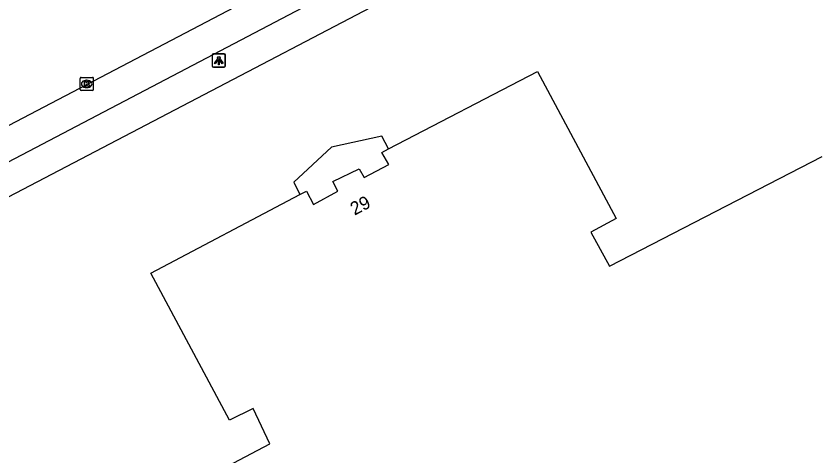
# Model space of a CAD drawing. Extents: x 157692 to 159670, y 381454 to 383289.
# Drawn here: x 158417.5 to 158478.6, y 381859.1 to 381892.5 of the extents above; entities that cross this region are included whole.
import ezdxf

# ---------------------------------------------------------------- set-up
doc = ezdxf.new("R2010")
doc.units = 0
for name, color, linetype in [('IMGEO_Kolk', 7, 'Continuous'), ('IMGEO_Lichtpunt', 7, 'Continuous'), ('IMGEO_Pand', 7, 'Continuous'), ('IMGEO_Pand_nummerreeks', 7, 'Continuous'), ('IMGEO_Pand_overbouw', 7, 'Continuous'), ('IMGEO_Rijbaan_lokaal_gesloten', 7, 'Continuous'), ('IMGEO_Voetpad_open', 7, 'Continuous')]:
    doc.layers.add(name, color=color, linetype=linetype)

msp = doc.modelspace()

# ---------------------------------------------------------------- linework, layer by layer
at = {"layer": 'IMGEO_Kolk'}
for p, q in [((158422.327, 381886.896), (158422.327, 381887.748)), ((158422.402, 381887.822), (158423.254, 381887.822)), ((158422.815, 381887.602), (158422.84, 381887.602)), ((158423.328, 381887.748), (158423.328, 381886.896)), ((158422.838, 381887.042), (158422.813, 381887.042)), ((158423.254, 381886.822), (158422.402, 381886.822))]:
    msp.add_line(p, q, dxfattribs=at)
for points in [[(158422.327, 381886.896), (158422.327, 381887.748)], [(158422.402, 381887.822), (158423.254, 381887.822)], [(158423.328, 381887.748), (158423.328, 381886.896)], [(158422.648, 381887.522), (158422.771, 381887.522), (158422.771, 381887.371), (158422.901, 381887.522), (158423.065, 381887.522), (158422.919, 381887.371), (158423.072, 381887.122), (158422.92, 381887.122), (158422.835, 381887.286), (158422.771, 381887.219), (158422.771, 381887.122), (158422.648, 381887.122), (158422.648, 381887.522)], [(158423.254, 381886.822), (158422.402, 381886.822)]]:
    msp.add_lwpolyline(points, dxfattribs=at)
for centre, start, end in [((158422.404, 381887.746), 91.55205, 178.44795), ((158422.404, 381887.746), 91.55205, 178.44795), ((158423.252, 381887.746), 1.55205, 88.44795), ((158423.252, 381887.746), 1.55205, 88.44795), ((158422.404, 381886.898), 181.55205, 268.44795), ((158422.404, 381886.898), 181.55205, 268.44795), ((158423.252, 381886.898), 271.55205, 358.44795), ((158423.252, 381886.898), 271.55205, 358.44795)]:
    msp.add_arc(centre, 0.0765, start, end, dxfattribs=at)
for centre, major_axis, ratio, start_param, end_param in [((158422.814, 381887.322), (-0.387, 0.002), 0.722429, 4.712389, 7.853982), ((158422.839, 381887.322), (-0.39, 0.002), 0.717154, 1.570796, 4.712389)]:
    msp.add_ellipse(centre, major_axis=major_axis, ratio=ratio, start_param=start_param, end_param=end_param, dxfattribs=at)
at = {"layer": 'IMGEO_Lichtpunt'}
for p, q in [((158432.34, 381889.486), (158432.34, 381888.679)), ((158432.34, 381889.486), (158432.34, 381888.679)), ((158432.351, 381889.512), (158432.351, 381888.705)), ((158432.351, 381889.512), (158432.351, 381888.705)), ((158433.242, 381889.581), (158432.434, 381889.581)), ((158433.242, 381889.581), (158432.434, 381889.581)), ((158433.253, 381889.607), (158432.445, 381889.607)), ((158433.253, 381889.607), (158432.445, 381889.607)), ((158433.336, 381888.679), (158433.336, 381889.486)), ((158433.336, 381888.679), (158433.336, 381889.486)), ((158433.347, 381888.705), (158433.347, 381889.512)), ((158433.347, 381888.705), (158433.347, 381889.512)), ((158432.434, 381888.585), (158433.242, 381888.585)), ((158432.434, 381888.585), (158433.242, 381888.585)), ((158432.445, 381888.611), (158433.253, 381888.611)), ((158432.445, 381888.611), (158433.253, 381888.611))]:
    msp.add_line(p, q, dxfattribs=at)
for points in [[(158432.714, 381889.15), (158432.753, 381889.122), (158432.565, 381888.86), (158432.527, 381888.887), (158432.714, 381889.15)], [(158432.725, 381889.176), (158432.764, 381889.148), (158432.576, 381888.886), (158432.538, 381888.913), (158432.725, 381889.176)], [(158432.816, 381889.102), (158432.863, 381889.102), (158432.863, 381888.78), (158432.816, 381888.78), (158432.816, 381889.102)], [(158432.827, 381889.128), (158432.874, 381889.128), (158432.874, 381888.806), (158432.827, 381888.806), (158432.827, 381889.128)], [(158432.926, 381889.122), (158432.964, 381889.149), (158433.151, 381888.887), (158433.112, 381888.859), (158432.926, 381889.122)], [(158432.937, 381889.148), (158432.975, 381889.175), (158433.162, 381888.913), (158433.123, 381888.885), (158432.937, 381889.148)]]:
    msp.add_lwpolyline(points, dxfattribs=at)
for centre in [(158432.85, 381889.31), (158432.839, 381889.284)]:
    msp.add_circle(centre, 0.0994, dxfattribs=at)
for centre, start, end in [((158432.434, 381889.486), 90, 180), ((158432.434, 381889.486), 90, 180), ((158432.445, 381889.512), 90, 180), ((158432.445, 381889.512), 90, 180), ((158433.242, 381889.486), 0, 90), ((158433.242, 381889.486), 0, 90), ((158433.253, 381889.512), 0, 90), ((158433.253, 381889.512), 0, 90), ((158432.434, 381888.679), 180, 270), ((158432.434, 381888.679), 180, 270), ((158432.445, 381888.705), 180, 270), ((158432.445, 381888.705), 180, 270), ((158433.242, 381888.679), 270, 0), ((158433.242, 381888.679), 270, 360), ((158433.253, 381888.705), 270, 0), ((158433.253, 381888.705), 270, 360)]:
    msp.add_arc(centre, 0.0946, start, end, dxfattribs=at)
at = {"layer": 'IMGEO_Pand'}
for points in [[(158500, 381822.082), (158469.028, 381805.901), (158462.391, 381818.606), (158444.04, 381808.991), (158423.833, 381847.573), (158421.513, 381852.002), (158436.722, 381860.027), (158435.442, 381862.688), (158433.661, 381861.806), (158427.69, 381872.962), (158438.993, 381878.936), (158439.486, 381879.197), (158440.018, 381878.184), (158441.862, 381879.176), (158441.494, 381879.914), (158443.493, 381880.877), (158443.857, 381880.213), (158445.739, 381881.199), (158445.21, 381882.131), (158445.724, 381882.398), (158457.019, 381888.266)], [(158457.019, 381888.266), (158462.982, 381877.104), (158461.052, 381876.066), (158462.48, 381873.488), (158478.602, 381881.811)]]:
    msp.add_lwpolyline(points, dxfattribs=at)
at = {"layer": 'IMGEO_Pand_overbouw'}
msp.add_lwpolyline([(158445.724, 381882.398), (158445.204, 381883.368), (158441.392, 381882.532), (158438.537, 381879.872), (158438.993, 381878.936), (158439.486, 381879.197), (158440.018, 381878.184), (158441.862, 381879.176), (158441.494, 381879.914), (158443.493, 381880.877), (158443.857, 381880.213), (158445.739, 381881.199), (158445.21, 381882.131)], close=True, dxfattribs=at)
at = {"layer": 'IMGEO_Rijbaan_lokaal_gesloten'}
msp.add_lwpolyline([(158287.161, 381816.195), (158340.401, 381844.12), (158462.964, 381908.32), (158465.398, 381909.602)], dxfattribs=at)
at = {"layer": 'IMGEO_Voetpad_open'}
for points in [[(158463.062, 381905.633), (158406.97, 381876.204)], [(158468.009, 381905.516), (158408.054, 381874.141)]]:
    msp.add_lwpolyline(points, dxfattribs=at)

# ---------------------------------------------------------------- texts
at = {"layer": 'IMGEO_Pand_nummerreeks'}
msp.add_text('29', height=1, rotation=27.55575, dxfattribs=at).set_placement((158443.139, 381877.324))

doc.saveas('drawing.dxf')
